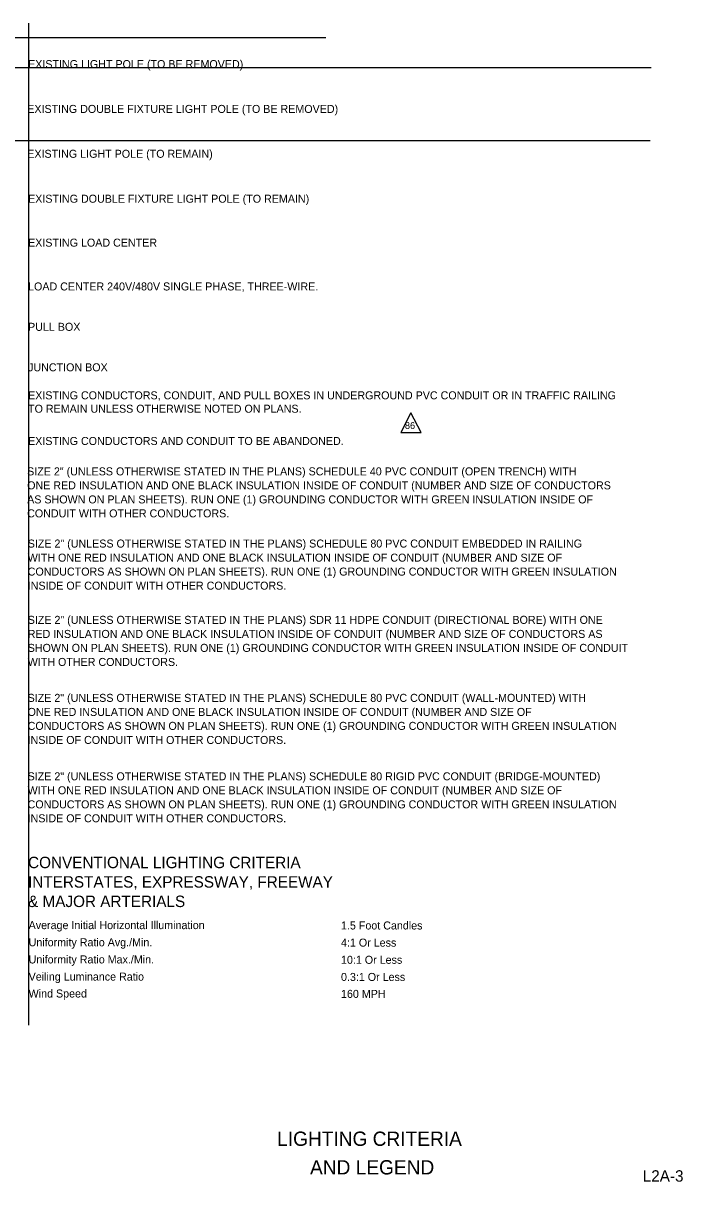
# Model space of a CAD drawing. Extents: x -0.7 to 15.2, y -0.9 to 9.6.
# Drawn here: x 9.38 to 15.15, y -0.65 to 9.48 of the extents above; entities that cross this region are included whole.
import ezdxf

# ---------------------------------------------------------------- set-up
doc = ezdxf.new("R2010")
doc.units = 0
for name, color, linetype in [('ActivePointCell_dp', 7, 'Continuous'), ('AdhocPoint_dp', 7, 'Continuous'), ('Cloud_dp', 7, 'Continuous'), ('TextMinor', 7, 'Continuous'), ('TextNotes', 7, 'Continuous'), ('TextShtNo', 7, 'Continuous')]:
    doc.layers.add(name, color=color, linetype=linetype)

msp = doc.modelspace()

# ---------------------------------------------------------------- linework, layer by layer
at = {"layer": 'ActivePointCell_dp'}
for p, q in [((9.43, 9.484), (9.43, 0.722)), ((14.876, 9.092), (-0.655, 9.092)), ((14.867, 8.456), (-0.599, 8.456))]:
    msp.add_line(p, q, dxfattribs=at)
at = {"layer": 'Cloud_dp'}
msp.add_lwpolyline([(12.775, 6.076), (12.687, 5.906), (12.863, 5.906)], close=True, dxfattribs=at)
at = {"layer": 'TextShtNo'}
msp.add_line((3.976, 9.358), (12.03, 9.358), dxfattribs=at)

# ---------------------------------------------------------------- texts
at = {"layer": 'AdhocPoint_dp'}
for s, p in [('EXISTING LIGHT POLE (TO BE REMOVED)', (9.425, 9.091)), ('EXISTING DOUBLE FIXTURE LIGHT POLE (TO BE REMOVED)', (9.418, 8.699)), ('EXISTING LIGHT POLE (TO REMAIN)', (9.418, 8.307)), ('EXISTING DOUBLE FIXTURE LIGHT POLE (TO REMAIN)', (9.425, 7.914)), ('EXISTING LOAD CENTER', (9.425, 7.53)), ('LOAD CENTER 240V/480V SINGLE PHASE, THREE-WIRE.', (9.425, 7.147)), ('PULL BOX', (9.425, 6.794)), ('JUNCTION BOX', (9.425, 6.44)), ('EXISTING CONDUCTORS, CONDUIT, AND PULL BOXES IN UNDERGROUND PVC CONDUIT OR IN TRAFFIC RAILING ', (9.425, 6.195)), ('TO REMAIN UNLESS OTHERWISE NOTED ON PLANS.', (9.425, 6.078)), ('EXISTING CONDUCTORS AND CONDUIT TO BE ABANDONED.', (9.425, 5.796)), ('SIZE 2" (UNLESS OTHERWISE STATED IN THE PLANS) SCHEDULE 40 PVC CONDUIT (OPEN TRENCH) WITH ', (9.417, 5.53)), ('ONE RED INSULATION AND ONE BLACK INSULATION INSIDE OF CONDUIT (NUMBER AND SIZE OF CONDUCTORS ', (9.417, 5.408)), ('AS SHOWN ON PLAN SHEETS). RUN ONE (1) GROUNDING CONDUCTOR WITH GREEN INSULATION INSIDE OF ', (9.417, 5.285)), ('CONDUIT WITH OTHER CONDUCTORS.', (9.417, 5.163)), ('SIZE 2" (UNLESS OTHERWISE STATED IN THE PLANS) SCHEDULE 80 PVC CONDUIT EMBEDDED IN RAILING ', (9.422, 4.899)), ('WITH ONE RED INSULATION AND ONE BLACK INSULATION INSIDE OF CONDUIT (NUMBER AND SIZE OF ', (9.422, 4.776)), ('CONDUCTORS AS SHOWN ON PLAN SHEETS). RUN ONE (1) GROUNDING CONDUCTOR WITH GREEN INSULATION ', (9.422, 4.654)), ('INSIDE OF CONDUIT WITH OTHER CONDUCTORS.', (9.422, 4.531)), ('SIZE 2" (UNLESS OTHERWISE STATED IN THE PLANS) SDR 11 HDPE CONDUIT (DIRECTIONAL BORE) WITH ONE ', (9.422, 4.232)), ('RED INSULATION AND ONE BLACK INSULATION INSIDE OF CONDUIT (NUMBER AND SIZE OF CONDUCTORS AS ', (9.422, 4.109)), ('SHOWN ON PLAN SHEETS). RUN ONE (1) GROUNDING CONDUCTOR WITH GREEN INSULATION INSIDE OF CONDUIT ', (9.422, 3.987)), ('WITH OTHER CONDUCTORS.', (9.422, 3.864)), ('SIZE 2" (UNLESS OTHERWISE STATED IN THE PLANS) SCHEDULE 80 PVC CONDUIT (WALL-MOUNTED) WITH ', (9.421, 3.55)), ('ONE RED INSULATION AND ONE BLACK INSULATION INSIDE OF CONDUIT (NUMBER AND SIZE OF ', (9.421, 3.427)), ('CONDUCTORS AS SHOWN ON PLAN SHEETS). RUN ONE (1) GROUNDING CONDUCTOR WITH GREEN INSULATION ', (9.421, 3.305)), ('INSIDE OF CONDUIT WITH OTHER CONDUCTORS.', (9.421, 3.182)), ('SIZE 2" (UNLESS OTHERWISE STATED IN THE PLANS) SCHEDULE 80 RIGID PVC CONDUIT (BRIDGE-MOUNTED) ', (9.421, 2.864)), ('WITH ONE RED INSULATION AND ONE BLACK INSULATION INSIDE OF CONDUIT (NUMBER AND SIZE OF ', (9.421, 2.742)), ('CONDUCTORS AS SHOWN ON PLAN SHEETS). RUN ONE (1) GROUNDING CONDUCTOR WITH GREEN INSULATION ', (9.421, 2.619)), ('INSIDE OF CONDUIT WITH OTHER CONDUCTORS.', (9.421, 2.497))]:
    msp.add_text(s, height=0.07, rotation=360, dxfattribs=at).set_placement(p)
for s, p in [('   LIGHTING CRITERIA    ', (11.465, -0.332)), ('       AND LEGEND       ', (11.567, -0.582))]:
    msp.add_text(s, height=0.125, dxfattribs=at).set_placement(p)
at = {"layer": 'Cloud_dp'}
msp.add_text('86', height=0.06, dxfattribs=at).set_placement((12.722, 5.936))
at = {"layer": 'TextMinor'}
for s, p in [('Average Initial Horizontal Illumination', (9.43, 1.563)), ('1.5 Foot Candles', (12.163, 1.56)), ('Uniformity Ratio Avg./Min.', (9.43, 1.413)), ('4:1 Or Less', (12.163, 1.41)), ('Uniformity Ratio Max./Min.', (9.43, 1.263)), ('10:1 Or Less', (12.163, 1.26)), ('Veiling Luminance Ratio', (9.43, 1.113)), ('0.3:1 Or Less', (12.163, 1.11)), ('Wind Speed', (9.43, 0.965)), ('160 MPH', (12.163, 0.962))]:
    msp.add_text(s, height=0.07, dxfattribs=at).set_placement(p)
at = {"layer": 'TextNotes'}
msp.add_text('L2A-3 ', height=0.1, rotation=360, dxfattribs=at).set_placement((14.803, -0.645))
at = {"layer": 'TextShtNo'}
for s, p in [('CONVENTIONAL LIGHTING CRITERIA', (9.425, 2.096)), ('INTERSTATES, EXPRESSWAY, FREEWAY', (9.425, 1.926)), ('& MAJOR ARTERIALS', (9.425, 1.756))]:
    msp.add_text(s, height=0.1, dxfattribs=at).set_placement(p)

doc.saveas('drawing.dxf')
